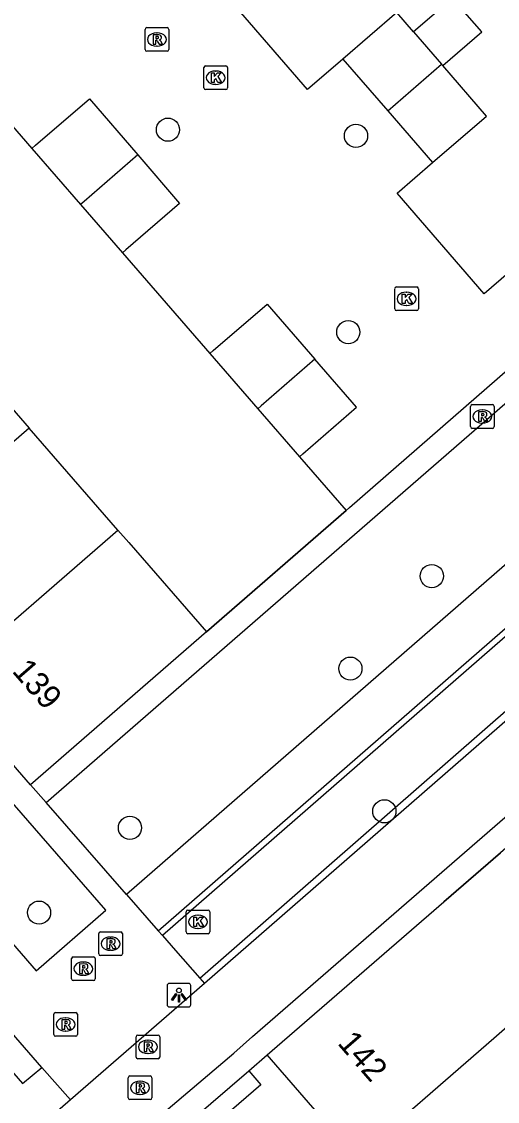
# Model space of a CAD drawing. Extents: x 155888 to 156864, y 383882 to 384671.
# Drawn here: x 156505.75 to 156525.81, y 384294.12 to 384339.71 of the extents above; entities that cross this region are included whole.
import ezdxf

# ---------------------------------------------------------------- set-up
doc = ezdxf.new("R2010")
doc.units = 0
for name, color, linetype in [('IMGEO_Boom', 7, 'Continuous'), ('IMGEO_Fietspad_gesloten', 7, 'Continuous'), ('IMGEO_Greppel_droge_sloot', 7, 'Continuous'), ('IMGEO_Haag', 7, 'Continuous'), ('IMGEO_Kolk', 7, 'Continuous'), ('IMGEO_Lichtpunt', 7, 'Continuous'), ('IMGEO_Muur', 7, 'Continuous'), ('IMGEO_Pand', 7, 'Continuous'), ('IMGEO_Pand_nummerreeks', 7, 'Continuous'), ('IMGEO_Rijbaan_lokaal_open', 7, 'Continuous'), ('IMGEO_Rioolput', 7, 'Continuous'), ('IMGEO_Voetpad_gesloten', 7, 'Continuous'), ('IMGEO_Voetpad_open', 7, 'Continuous')]:
    doc.layers.add(name, color=color, linetype=linetype)

msp = doc.modelspace()

# ---------------------------------------------------------------- linework, layer by layer
at = {"layer": 'IMGEO_Boom'}
for centre in [(156511.919, 384335.147), (156519.85, 384334.887), (156519.526, 384326.599), (156523.048, 384316.3), (156519.614, 384312.395), (156521.046, 384306.37), (156510.317, 384305.673), (156506.482, 384302.094)]:
    msp.add_circle(centre, 0.489, dxfattribs=at)
at = {"layer": 'IMGEO_Fietspad_gesloten'}
for points in [[(156554.933, 384335.268), (156551.774, 384332.513), (156513.461, 384299.101)], [(156511.459, 384293.409), (156514.691, 384296.154), (156515.48, 384296.862), (156553.811, 384330.161), (156554.603, 384330.849), (156557.035, 384332.96)], [(156513.461, 384299.101), (156507.808, 384294.187)], [(156507.808, 384294.187), (156504.978, 384291.727)]]:
    msp.add_lwpolyline(points, dxfattribs=at)
at = {"layer": 'IMGEO_Greppel_droge_sloot'}
msp.add_lwpolyline([(156513.259, 384299.332), (156551.773, 384332.999), (156550.337, 384334.838), (156511.686, 384301.131)], dxfattribs=at)
at = {"layer": 'IMGEO_Haag'}
for points in [[(156506.779, 384306.742), (156527.957, 384325.168)], [(156519.431, 384319.075), (156513.543, 384313.947)], [(156512.127, 384292.651), (156515.326, 384295.42)]]:
    msp.add_lwpolyline(points, dxfattribs=at)
at = {"layer": 'IMGEO_Kolk'}
for p, q in [((156513.431, 384336.915), (156513.431, 384337.767)), ((156513.506, 384337.841), (156514.358, 384337.841)), ((156513.919, 384337.621), (156513.944, 384337.621)), ((156514.432, 384337.767), (156514.432, 384336.915)), ((156513.942, 384337.061), (156513.917, 384337.061)), ((156514.358, 384336.841), (156513.506, 384336.841)), ((156521.483, 384327.583), (156521.483, 384328.435)), ((156521.558, 384328.509), (156522.41, 384328.509)), ((156522.484, 384328.435), (156522.484, 384327.583)), ((156521.971, 384328.289), (156521.996, 384328.289)), ((156522.41, 384327.509), (156521.558, 384327.509)), ((156521.994, 384327.729), (156521.969, 384327.729)), ((156512.685, 384301.276), (156512.685, 384302.128)), ((156512.76, 384302.202), (156513.612, 384302.202)), ((156513.173, 384301.982), (156513.198, 384301.982)), ((156513.686, 384302.128), (156513.686, 384301.276)), ((156513.612, 384301.202), (156512.76, 384301.202)), ((156513.196, 384301.422), (156513.171, 384301.422))]:
    msp.add_line(p, q, dxfattribs=at)
for points in [[(156513.431, 384336.915), (156513.431, 384337.767)], [(156513.506, 384337.841), (156514.358, 384337.841)], [(156513.752, 384337.541), (156513.875, 384337.541), (156513.875, 384337.39), (156514.005, 384337.541), (156514.169, 384337.541), (156514.023, 384337.39), (156514.176, 384337.141), (156514.024, 384337.141), (156513.939, 384337.305), (156513.875, 384337.238), (156513.875, 384337.141), (156513.752, 384337.141), (156513.752, 384337.541)], [(156514.432, 384337.767), (156514.432, 384336.915)], [(156514.358, 384336.841), (156513.506, 384336.841)], [(156521.483, 384327.583), (156521.483, 384328.435)], [(156521.558, 384328.509), (156522.41, 384328.509)], [(156522.484, 384328.435), (156522.484, 384327.583)], [(156521.804, 384328.209), (156521.927, 384328.209), (156521.927, 384328.058), (156522.057, 384328.209), (156522.221, 384328.209), (156522.075, 384328.058), (156522.228, 384327.809), (156522.076, 384327.809), (156521.991, 384327.973), (156521.927, 384327.906), (156521.927, 384327.809), (156521.804, 384327.809), (156521.804, 384328.209)], [(156522.41, 384327.509), (156521.558, 384327.509)], [(156512.685, 384301.276), (156512.685, 384302.128)], [(156512.76, 384302.202), (156513.612, 384302.202)], [(156513.686, 384302.128), (156513.686, 384301.276)], [(156513.006, 384301.902), (156513.129, 384301.902), (156513.129, 384301.751), (156513.259, 384301.902), (156513.423, 384301.902), (156513.277, 384301.751), (156513.43, 384301.502), (156513.278, 384301.502), (156513.193, 384301.666), (156513.129, 384301.599), (156513.129, 384301.502), (156513.006, 384301.502), (156513.006, 384301.902)], [(156513.612, 384301.202), (156512.76, 384301.202)]]:
    msp.add_lwpolyline(points, dxfattribs=at)
for centre, start, end in [((156513.508, 384337.765), 91.552, 178.448), ((156513.508, 384337.765), 91.552, 178.448), ((156514.356, 384337.765), 1.552, 88.448), ((156514.356, 384337.765), 1.552, 88.448), ((156513.508, 384336.917), 181.552, 268.448), ((156513.508, 384336.917), 181.552, 268.448), ((156514.356, 384336.917), 271.552, 358.448), ((156514.356, 384336.917), 271.552, 358.448), ((156521.56, 384328.433), 91.552, 178.448), ((156521.56, 384328.433), 91.552, 178.448), ((156522.408, 384328.433), 1.552, 88.448), ((156522.408, 384328.433), 1.552, 88.448), ((156521.56, 384327.585), 181.552, 268.448), ((156521.56, 384327.585), 181.552, 268.448), ((156522.408, 384327.585), 271.552, 358.448), ((156522.408, 384327.585), 271.552, 358.448), ((156512.762, 384302.126), 91.552, 178.448), ((156512.762, 384302.126), 91.552, 178.448), ((156513.61, 384302.126), 1.552, 88.448), ((156513.61, 384302.126), 1.552, 88.448), ((156512.762, 384301.278), 181.552, 268.448), ((156512.762, 384301.278), 181.552, 268.448), ((156513.61, 384301.278), 271.552, 358.448), ((156513.61, 384301.278), 271.552, 358.448)]:
    msp.add_arc(centre, 0.0765, start, end, dxfattribs=at)
for centre, major_axis, ratio, start_param, end_param in [((156513.918, 384337.341), (-0.387, 0.002), 0.722429, 4.712389, 7.853982), ((156513.943, 384337.341), (-0.39, 0.002), 0.717154, 1.570796, 4.712389), ((156521.97, 384328.009), (-0.387, 0.002), 0.722429, 4.712389, 7.853982), ((156521.995, 384328.009), (-0.39, 0.002), 0.717154, 1.570796, 4.712389), ((156513.172, 384301.702), (-0.387, 0.002), 0.722429, 4.712389, 7.853982), ((156513.197, 384301.702), (-0.39, 0.002), 0.717154, 1.570796, 4.712389)]:
    msp.add_ellipse(centre, major_axis=major_axis, ratio=ratio, start_param=start_param, end_param=end_param, dxfattribs=at)
at = {"layer": 'IMGEO_Lichtpunt'}
for p, q in [((156511.884, 384299.012), (156511.884, 384298.205)), ((156511.884, 384299.012), (156511.884, 384298.205)), ((156512.786, 384299.107), (156511.978, 384299.107)), ((156512.786, 384299.107), (156511.978, 384299.107)), ((156512.88, 384298.205), (156512.88, 384299.012)), ((156512.88, 384298.205), (156512.88, 384299.012)), ((156511.978, 384298.111), (156512.786, 384298.111)), ((156511.978, 384298.111), (156512.786, 384298.111))]:
    msp.add_line(p, q, dxfattribs=at)
for points in [[(156512.258, 384298.676), (156512.297, 384298.648), (156512.109, 384298.386), (156512.071, 384298.413), (156512.258, 384298.676)], [(156512.36, 384298.628), (156512.407, 384298.628), (156512.407, 384298.306), (156512.36, 384298.306), (156512.36, 384298.628)], [(156512.47, 384298.648), (156512.508, 384298.675), (156512.695, 384298.413), (156512.656, 384298.385), (156512.47, 384298.648)]]:
    msp.add_lwpolyline(points, dxfattribs=at)
msp.add_circle((156512.383, 384298.81), 0.0994, dxfattribs=at)
for centre, start, end in [((156511.978, 384299.012), 90, 180), ((156511.978, 384299.012), 90, 180), ((156512.786, 384299.012), 0, 90), ((156512.786, 384299.012), 0, 90), ((156511.978, 384298.205), 180, 270), ((156511.978, 384298.205), 180, 270), ((156512.786, 384298.205), 270, 0), ((156512.786, 384298.205), 270, 360)]:
    msp.add_arc(centre, 0.0946, start, end, dxfattribs=at)
at = {"layer": 'IMGEO_Muur'}
for points in [[(156513.543, 384313.947), (156519.431, 384319.075)], [(156529.456, 384307.681), (156525.947, 384304.624), (156523.554, 384302.55)]]:
    msp.add_lwpolyline(points, dxfattribs=at)
at = {"layer": 'IMGEO_Pand'}
for points in [[(156523.506, 384337.853), (156525.153, 384339.278), (156523.917, 384340.706), (156522.27, 384339.281)], [(156522.27, 384339.281), (156521.567, 384340.093), (156519.298, 384338.13)], [(156522.27, 384339.281), (156523.459, 384337.907)], [(156519.298, 384338.13), (156521.196, 384335.936)], [(156521.196, 384335.936), (156523.459, 384337.907)], [(156523.083, 384333.756), (156525.352, 384335.719), (156523.506, 384337.853)], [(156523.459, 384337.907), (156523.506, 384337.853)], [(156506.171, 384334.359), (156506.329, 384334.496), (156508.603, 384336.453), (156510.643, 384334.084)], [(156521.196, 384335.936), (156523.083, 384333.756)], [(156506.171, 384334.359), (156508.229, 384331.987)], [(156510.643, 384334.084), (156508.378, 384332.116), (156508.229, 384331.987)], [(156510.643, 384334.084), (156512.41, 384332.031), (156510.136, 384330.074), (156509.995, 384329.951)], [(156508.229, 384331.987), (156509.995, 384329.951)], [(156513.688, 384325.694), (156513.833, 384325.82), (156516.1, 384327.785), (156518.116, 384325.459)], [(156502.325, 384326.857), (156506.069, 384322.549)], [(156513.688, 384325.694), (156515.708, 384323.366)], [(156518.116, 384325.459), (156515.852, 384323.491), (156515.708, 384323.366)], [(156517.465, 384321.341), (156517.608, 384321.465), (156519.875, 384323.43), (156518.116, 384325.459)], [(156515.708, 384323.366), (156517.465, 384321.341)], [(156506.069, 384322.549), (156500, 384317.276), (156498.645, 384316.099)], [(156509.811, 384318.244), (156506.069, 384322.549)], [(156502.386, 384311.794), (156509.811, 384318.244)], [(156509.811, 384318.244), (156510.264, 384317.722), (156513.543, 384313.947)], [(156513.543, 384313.947), (156506.121, 384307.495)], [(156506.121, 384307.495), (156502.386, 384311.794)], [(156516.106, 384296.095), (156523.554, 384302.55), (156525.947, 384304.624)], [(156527.315, 384298.209), (156525.337, 384296.491), (156519.875, 384291.745)], [(156519.875, 384291.745), (156516.106, 384296.095)]]:
    msp.add_lwpolyline(points, dxfattribs=at)
at = {"layer": 'IMGEO_Rijbaan_lokaal_open'}
for points in [[(156519.298, 384338.13), (156517.801, 384336.841), (156514.179, 384341.048), (156515.658, 384342.346)], [(156502.546, 384338.536), (156506.171, 384334.359)], [(156527.003, 384329.729), (156525.26, 384328.215), (156521.587, 384332.461), (156523.083, 384333.756)], [(156509.995, 384329.951), (156513.688, 384325.694)], [(156519.431, 384319.075), (156519.574, 384319.199), (156527.341, 384325.962)], [(156517.465, 384321.341), (156519.431, 384319.075)]]:
    msp.add_lwpolyline(points, dxfattribs=at)
at = {"layer": 'IMGEO_Rioolput'}
for p, q in [((156510.952, 384338.531), (156510.952, 384339.383)), ((156511.027, 384339.457), (156511.879, 384339.457)), ((156511.953, 384339.383), (156511.953, 384338.531)), ((156511.44, 384339.237), (156511.465, 384339.237)), ((156511.879, 384338.457), (156511.027, 384338.457)), ((156511.463, 384338.677), (156511.438, 384338.677)), ((156524.679, 384322.612), (156524.679, 384323.464)), ((156524.754, 384323.538), (156525.606, 384323.538)), ((156525.68, 384323.464), (156525.68, 384322.612)), ((156525.167, 384323.318), (156525.192, 384323.318)), ((156525.606, 384322.538), (156524.754, 384322.538)), ((156525.19, 384322.758), (156525.165, 384322.758)), ((156509, 384300.356), (156509, 384301.208)), ((156509.075, 384301.282), (156509.927, 384301.282)), ((156509.488, 384301.062), (156509.513, 384301.062)), ((156510.001, 384301.208), (156510.001, 384300.356)), ((156507.849, 384299.3), (156507.849, 384300.152)), ((156507.924, 384300.226), (156508.776, 384300.226)), ((156508.85, 384300.152), (156508.85, 384299.3)), ((156509.927, 384300.282), (156509.075, 384300.282)), ((156509.511, 384300.502), (156509.486, 384300.502)), ((156508.337, 384300.006), (156508.362, 384300.006)), ((156508.776, 384299.226), (156507.924, 384299.226)), ((156508.36, 384299.446), (156508.335, 384299.446)), ((156507.178, 384297.874), (156508.03, 384297.874)), ((156507.103, 384296.948), (156507.103, 384297.8)), ((156507.591, 384297.654), (156507.616, 384297.654)), ((156508.104, 384297.8), (156508.104, 384296.948)), ((156507.614, 384297.094), (156507.589, 384297.094)), ((156508.03, 384296.874), (156507.178, 384296.874)), ((156510.573, 384295.998), (156510.573, 384296.85)), ((156510.648, 384296.924), (156511.5, 384296.924)), ((156511.061, 384296.704), (156511.086, 384296.704)), ((156511.574, 384296.85), (156511.574, 384295.998)), ((156511.084, 384296.144), (156511.059, 384296.144)), ((156511.5, 384295.924), (156510.648, 384295.924)), ((156510.241, 384294.272), (156510.241, 384295.124)), ((156510.316, 384295.198), (156511.168, 384295.198)), ((156511.242, 384295.124), (156511.242, 384294.272)), ((156510.729, 384294.978), (156510.754, 384294.978)), ((156511.168, 384294.198), (156510.316, 384294.198)), ((156510.752, 384294.418), (156510.727, 384294.418))]:
    msp.add_line(p, q, dxfattribs=at)
for points in [[(156510.952, 384338.531), (156510.952, 384339.383)], [(156511.027, 384339.457), (156511.879, 384339.457)], [(156511.953, 384339.383), (156511.953, 384338.531)], [(156511.541, 384339.155), (156511.289, 384339.157), (156511.289, 384338.757)], [(156511.289, 384338.757), (156511.413, 384338.757), (156511.413, 384338.919), (156511.424, 384338.919)], [(156511.467, 384339.076), (156511.413, 384339.076), (156511.413, 384338.995)], [(156511.413, 384338.995), (156511.465, 384338.995)], [(156511.471, 384338.89), (156511.542, 384338.757), (156511.682, 384338.757), (156511.617, 384338.883)], [(156511.879, 384338.457), (156511.027, 384338.457)], [(156524.679, 384322.612), (156524.679, 384323.464)], [(156524.754, 384323.538), (156525.606, 384323.538)], [(156525.68, 384323.464), (156525.68, 384322.612)], [(156525.268, 384323.236), (156525.016, 384323.238), (156525.016, 384322.838)], [(156525.016, 384322.838), (156525.14, 384322.838), (156525.14, 384323), (156525.151, 384323)], [(156525.194, 384323.157), (156525.14, 384323.157), (156525.14, 384323.076)], [(156525.14, 384323.076), (156525.192, 384323.076)], [(156525.198, 384322.971), (156525.269, 384322.838), (156525.409, 384322.838), (156525.344, 384322.964)], [(156525.606, 384322.538), (156524.754, 384322.538)], [(156509, 384300.356), (156509, 384301.208)], [(156509.075, 384301.282), (156509.927, 384301.282)], [(156510.001, 384301.208), (156510.001, 384300.356)], [(156509.589, 384300.98), (156509.337, 384300.982), (156509.337, 384300.582)], [(156509.337, 384300.582), (156509.461, 384300.582), (156509.461, 384300.744), (156509.472, 384300.744)], [(156509.515, 384300.901), (156509.461, 384300.901), (156509.461, 384300.82)], [(156509.461, 384300.82), (156509.513, 384300.82)], [(156509.519, 384300.715), (156509.59, 384300.582), (156509.73, 384300.582), (156509.665, 384300.708)], [(156507.849, 384299.3), (156507.849, 384300.152)], [(156507.924, 384300.226), (156508.776, 384300.226)], [(156508.85, 384300.152), (156508.85, 384299.3)], [(156509.927, 384300.282), (156509.075, 384300.282)], [(156508.438, 384299.924), (156508.186, 384299.926), (156508.186, 384299.526)], [(156508.186, 384299.526), (156508.31, 384299.526), (156508.31, 384299.688), (156508.321, 384299.688)], [(156508.364, 384299.845), (156508.31, 384299.845), (156508.31, 384299.764)], [(156508.31, 384299.764), (156508.362, 384299.764)], [(156508.776, 384299.226), (156507.924, 384299.226)], [(156508.368, 384299.659), (156508.439, 384299.526), (156508.579, 384299.526), (156508.514, 384299.652)], [(156507.178, 384297.874), (156508.03, 384297.874)], [(156507.103, 384296.948), (156507.103, 384297.8)], [(156507.692, 384297.572), (156507.44, 384297.574), (156507.44, 384297.174)], [(156507.618, 384297.493), (156507.564, 384297.493), (156507.564, 384297.412)], [(156507.564, 384297.412), (156507.616, 384297.412)], [(156508.104, 384297.8), (156508.104, 384296.948)], [(156507.44, 384297.174), (156507.564, 384297.174), (156507.564, 384297.336), (156507.575, 384297.336)], [(156507.622, 384297.307), (156507.693, 384297.174), (156507.833, 384297.174), (156507.768, 384297.3)], [(156508.03, 384296.874), (156507.178, 384296.874)], [(156510.573, 384295.998), (156510.573, 384296.85)], [(156510.648, 384296.924), (156511.5, 384296.924)], [(156511.162, 384296.622), (156510.91, 384296.624), (156510.91, 384296.224)], [(156511.088, 384296.543), (156511.034, 384296.543), (156511.034, 384296.462)], [(156511.574, 384296.85), (156511.574, 384295.998)], [(156510.91, 384296.224), (156511.034, 384296.224), (156511.034, 384296.386), (156511.045, 384296.386)], [(156511.034, 384296.462), (156511.086, 384296.462)], [(156511.092, 384296.357), (156511.163, 384296.224), (156511.303, 384296.224), (156511.238, 384296.35)], [(156511.5, 384295.924), (156510.648, 384295.924)], [(156510.241, 384294.272), (156510.241, 384295.124)], [(156510.316, 384295.198), (156511.168, 384295.198)], [(156511.242, 384295.124), (156511.242, 384294.272)], [(156510.83, 384294.896), (156510.578, 384294.898), (156510.578, 384294.498)], [(156510.578, 384294.498), (156510.702, 384294.498), (156510.702, 384294.66), (156510.713, 384294.66)], [(156510.756, 384294.817), (156510.702, 384294.817), (156510.702, 384294.736)], [(156510.702, 384294.736), (156510.754, 384294.736)], [(156511.168, 384294.198), (156510.316, 384294.198)], [(156510.76, 384294.631), (156510.831, 384294.498), (156510.971, 384294.498), (156510.906, 384294.624)]]:
    msp.add_lwpolyline(points, dxfattribs=at)
for centre, radius, start, end in [((156511.029, 384339.381), 0.0765, 91.552, 178.448), ((156511.029, 384339.381), 0.0765, 91.552, 178.448), ((156511.877, 384339.381), 0.0765, 1.552, 88.448), ((156511.877, 384339.381), 0.0765, 1.552, 88.448), ((156511.423, 384338.866), 0.0533, 26.0293, 88.6989), ((156511.449, 384339.184), 0.19, 274.7715, 282.9687), ((156511.473, 384338.98), 0.0964, 77.0061, 93.1865), ((156511.487, 384339.037), 0.0378, 276.6634, 79.6772), ((156511.54, 384339.045), 0.109, 350.3612, 89.416), ((156511.538, 384339.045), 0.112, 277.5842, 350.9817), ((156511.522, 384338.83), 0.108, 29.5134, 73.7905), ((156511.029, 384338.533), 0.0765, 181.552, 268.448), ((156511.029, 384338.533), 0.0765, 181.552, 268.448), ((156511.877, 384338.533), 0.0765, 271.552, 358.448), ((156511.877, 384338.533), 0.0765, 271.552, 358.448), ((156524.756, 384323.462), 0.0765, 91.552, 178.448), ((156524.756, 384323.462), 0.0765, 91.552, 178.448), ((156525.604, 384323.462), 0.0765, 1.552, 88.448), ((156525.604, 384323.462), 0.0765, 1.552, 88.448), ((156525.15, 384322.947), 0.0533, 26.0293, 88.6989), ((156525.176, 384323.265), 0.19, 274.7715, 282.9687), ((156525.2, 384323.061), 0.0964, 77.0061, 93.1865), ((156525.214, 384323.118), 0.0378, 276.6634, 79.6772), ((156525.267, 384323.126), 0.109, 350.3612, 89.416), ((156525.265, 384323.126), 0.112, 277.5842, 350.9817), ((156525.249, 384322.911), 0.108, 29.5134, 73.7905), ((156524.756, 384322.614), 0.0765, 181.552, 268.448), ((156524.756, 384322.614), 0.0765, 181.552, 268.448), ((156525.604, 384322.614), 0.0765, 271.552, 358.448), ((156525.604, 384322.614), 0.0765, 271.552, 358.448), ((156509.077, 384301.206), 0.0765, 91.552, 178.448), ((156509.077, 384301.206), 0.0765, 91.552, 178.448), ((156509.925, 384301.206), 0.0765, 1.552, 88.448), ((156509.925, 384301.206), 0.0765, 1.552, 88.448), ((156509.471, 384300.691), 0.0533, 26.0293, 88.6989), ((156509.497, 384301.009), 0.19, 274.7715, 282.9687), ((156509.521, 384300.805), 0.0964, 77.0061, 93.1865), ((156509.535, 384300.862), 0.0378, 276.6634, 79.6772), ((156509.588, 384300.87), 0.109, 350.3612, 89.416), ((156509.586, 384300.87), 0.112, 277.5842, 350.9817), ((156509.57, 384300.655), 0.108, 29.5134, 73.7905), ((156507.926, 384300.15), 0.0765, 91.552, 178.448), ((156507.926, 384300.15), 0.0765, 91.552, 178.448), ((156508.774, 384300.15), 0.0765, 1.552, 88.448), ((156508.774, 384300.15), 0.0765, 1.552, 88.448), ((156509.077, 384300.358), 0.0765, 181.552, 268.448), ((156509.077, 384300.358), 0.0765, 181.552, 268.448), ((156509.925, 384300.358), 0.0765, 271.552, 358.448), ((156509.925, 384300.358), 0.0765, 271.552, 358.448), ((156508.32, 384299.635), 0.0533, 26.0293, 88.6989), ((156508.346, 384299.953), 0.19, 274.7715, 282.9687), ((156508.37, 384299.749), 0.0964, 77.0061, 93.1865), ((156508.384, 384299.806), 0.0378, 276.6634, 79.6772), ((156508.437, 384299.814), 0.109, 350.3612, 89.416), ((156508.435, 384299.814), 0.112, 277.5842, 350.9817), ((156508.419, 384299.599), 0.108, 29.5134, 73.7905), ((156507.926, 384299.302), 0.0765, 181.552, 268.448), ((156507.926, 384299.302), 0.0765, 181.552, 268.448), ((156508.774, 384299.302), 0.0765, 271.552, 358.448), ((156508.774, 384299.302), 0.0765, 271.552, 358.448), ((156507.18, 384297.798), 0.0765, 91.552, 178.448), ((156507.18, 384297.798), 0.0765, 91.552, 178.448), ((156508.028, 384297.798), 0.0765, 1.552, 88.448), ((156508.028, 384297.798), 0.0765, 1.552, 88.448), ((156507.6, 384297.601), 0.19, 274.7715, 282.9687), ((156507.624, 384297.397), 0.0964, 77.0061, 93.1865), ((156507.638, 384297.454), 0.0378, 276.6634, 79.6772), ((156507.691, 384297.462), 0.109, 350.3612, 89.416), ((156507.689, 384297.462), 0.112, 277.5842, 350.9817), ((156507.18, 384296.95), 0.0765, 181.552, 268.448), ((156507.18, 384296.95), 0.0765, 181.552, 268.448), ((156507.574, 384297.283), 0.0533, 26.0293, 88.6989), ((156507.673, 384297.247), 0.108, 29.5134, 73.7905), ((156508.028, 384296.95), 0.0765, 271.552, 358.448), ((156508.028, 384296.95), 0.0765, 271.552, 358.448), ((156510.65, 384296.848), 0.0765, 91.552, 178.448), ((156510.65, 384296.848), 0.0765, 91.552, 178.448), ((156511.094, 384296.447), 0.0964, 77.0061, 93.1865), ((156511.108, 384296.504), 0.0378, 276.6634, 79.6772), ((156511.161, 384296.512), 0.109, 350.3612, 89.416), ((156511.159, 384296.512), 0.112, 277.5842, 350.9817), ((156511.498, 384296.848), 0.0765, 1.552, 88.448), ((156511.498, 384296.848), 0.0765, 1.552, 88.448), ((156511.044, 384296.333), 0.0533, 26.0293, 88.6989), ((156511.07, 384296.651), 0.19, 274.7715, 282.9687), ((156511.143, 384296.297), 0.108, 29.5134, 73.7905), ((156510.65, 384296), 0.0765, 181.552, 268.448), ((156510.65, 384296), 0.0765, 181.552, 268.448), ((156511.498, 384296), 0.0765, 271.552, 358.448), ((156511.498, 384296), 0.0765, 271.552, 358.448), ((156510.318, 384295.122), 0.0765, 91.552, 178.448), ((156510.318, 384295.122), 0.0765, 91.552, 178.448), ((156511.166, 384295.122), 0.0765, 1.552, 88.448), ((156511.166, 384295.122), 0.0765, 1.552, 88.448), ((156510.712, 384294.607), 0.0533, 26.0293, 88.6989), ((156510.738, 384294.925), 0.19, 274.7715, 282.9687), ((156510.762, 384294.721), 0.0964, 77.0061, 93.1865), ((156510.776, 384294.778), 0.0378, 276.6634, 79.6772), ((156510.829, 384294.786), 0.109, 350.3612, 89.416), ((156510.827, 384294.786), 0.112, 277.5842, 350.9817), ((156510.811, 384294.571), 0.108, 29.5134, 73.7905), ((156510.318, 384294.274), 0.0765, 181.552, 268.448), ((156510.318, 384294.274), 0.0765, 181.552, 268.448), ((156511.166, 384294.274), 0.0765, 271.552, 358.448), ((156511.166, 384294.274), 0.0765, 271.552, 358.448)]:
    msp.add_arc(centre, radius, start, end, dxfattribs=at)
for centre, major_axis, ratio, start_param, end_param in [((156511.439, 384338.957), (-0.387, 0.002), 0.722429, 4.712389, 7.853982), ((156511.464, 384338.957), (-0.39, 0.002), 0.717154, 1.570796, 4.712389), ((156525.166, 384323.038), (-0.387, 0.002), 0.722429, 4.712389, 7.853982), ((156525.191, 384323.038), (-0.39, 0.002), 0.717154, 1.570796, 4.712389), ((156509.487, 384300.782), (-0.387, 0.002), 0.722429, 4.712389, 7.853982), ((156509.512, 384300.782), (-0.39, 0.002), 0.717154, 1.570796, 4.712389), ((156508.336, 384299.726), (-0.387, 0.002), 0.722429, 4.712389, 7.853982), ((156508.361, 384299.726), (-0.39, 0.002), 0.717154, 1.570796, 4.712389), ((156507.59, 384297.374), (-0.387, 0.002), 0.722429, 4.712389, 7.853982), ((156507.615, 384297.374), (-0.39, 0.002), 0.717154, 1.570796, 4.712389), ((156511.06, 384296.424), (-0.387, 0.002), 0.722429, 4.712389, 7.853982), ((156511.085, 384296.424), (-0.39, 0.002), 0.717154, 1.570796, 4.712389), ((156510.728, 384294.698), (-0.387, 0.002), 0.722429, 4.712389, 7.853982), ((156510.753, 384294.698), (-0.39, 0.002), 0.717154, 1.570796, 4.712389)]:
    msp.add_ellipse(centre, major_axis=major_axis, ratio=ratio, start_param=start_param, end_param=end_param, dxfattribs=at)
at = {"layer": 'IMGEO_Voetpad_gesloten'}
for points in [[(156511.511, 384301.331), (156549.833, 384334.752), (156552.702, 384337.254)], [(156531.31, 384321.278), (156510.173, 384302.862)], [(156510.173, 384302.862), (156511.511, 384301.331)]]:
    msp.add_lwpolyline(points, dxfattribs=at)
at = {"layer": 'IMGEO_Voetpad_open'}
for points in [[(156485.228, 384320.167), (156484.42, 384319.476), (156500, 384301.535), (156505.785, 384294.873), (156506.593, 384295.554)], [(156506.593, 384295.554), (156500, 384303.149), (156485.228, 384320.167)], [(156502.706, 384309.762), (156500, 384307.468), (156499.751, 384307.257), (156500, 384306.97), (156506.356, 384299.632), (156509.3, 384302.198), (156502.706, 384309.762)], [(156506.121, 384307.495), (156506.779, 384306.742)], [(156510.173, 384302.862), (156506.779, 384306.742)], [(156511.511, 384301.331), (156511.686, 384301.131)], [(156511.686, 384301.131), (156512.238, 384300.5), (156513.259, 384299.332)], [(156513.259, 384299.332), (156513.461, 384299.101)], [(156515.326, 384295.42), (156516.106, 384296.095)], [(156506.593, 384295.554), (156507.808, 384294.187)], [(156515.326, 384295.42), (156515.838, 384294.828), (156512.64, 384292.07), (156512.127, 384292.651)]]:
    msp.add_lwpolyline(points, dxfattribs=at)

# ---------------------------------------------------------------- texts
at = {"layer": 'IMGEO_Pand_nummerreeks'}
for s, rotation, p in [('139', 310.9894, (156505.309, 384312.272)), ('142', 310.9491, (156519.036, 384296.565))]:
    msp.add_text(s, height=1, rotation=rotation, dxfattribs=at).set_placement(p)

doc.saveas('drawing.dxf')
